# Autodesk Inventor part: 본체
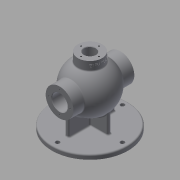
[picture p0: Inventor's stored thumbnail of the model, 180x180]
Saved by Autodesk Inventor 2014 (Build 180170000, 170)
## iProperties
Created: 2020-08
Part Number: 본체
Material: Generic
Document SubType Name: Modeling
Designer: kh
Density: 1 g/cm^3
Appearance: Default
Mass: 649.145 g
Surface Area: 1342.58 cm^2
Volume: 649.145 cm^3
Author: kh
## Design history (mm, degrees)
sketch "Sketch1"
  geometry: C1 r 85 at (0, 0); 1 further point
  constraints: 1 centre point, 1 coincident
  dimensions: "d0" = 170 diameter of C1
extrude "Extrusion1" new body sketch "Sketch1" distance "d1" = 10; taper "d2" = 0 deg
sketch "Sketch2"
  geometry: L1 (-55.535, 85)-(55.001, 85); L2 (-68, 102.5)-(-52, 102.5); L3 (-52, 102.5)-(-52, 103.5); L4 (-52, 103.5)-(-50.25, 103.5); L5 (-50.25, 103.5)-(-50.25, 102.5); L6 (-50.25, 102.5)-(-39.278, 102.5); L7 (68, 102.5)-(39.278, 102.5); L8 (-68, 102.5)-(-68, 116); L9 (-68, 116)-(-42.988, 116); L10 (68, 102.5)-(68, 116); L11 (68, 116)-(42.988, 116); A1 r 43 centre (0, 85) between (39.278, 102.5) and (-39.278, 102.5); A2 r 53 centre (0, 85) between (42.988, 116) and (-42.988, 116); 1 further point
  constraints: 22 end point, 5 perpendicular, 4 point on circle, 3 collinear, 3 parallel, 2 centre point, 2 point on line, 1 concentric, 1 horizontal, 1 vertical alignment
  dimensions: "d3" = 43 radius of A1; "d4" = 53 radius of A2; "d5" = 85 vertical distance of L1.end point (0, 0); "d6" = 35 diameter of L2 L1; "d7" = 37 diameter of L4 L1; "d8" = 35 diameter of L6 L1; "d9" = 35 diameter of L7 L1; "d10" = 62 diameter of L9 L1; "d11" = 62 diameter of L11 L1; "d12" = 16 distance of L2.start L2.end; "d13" = 1.75 distance of L3.end L4.end; "d14" = 136 distance between parallel lines of L10 L8
revolve "Revolution1" sketch "Sketch2" stored, may be unused: angle "d15" = 90 deg
workplane "Work Plane1"
sketch "Sketch3"
  geometry: C1 r 27 at (0, 0); 1 further point
  constraints: 1 centre point, 1 coincident
  dimensions: "d17" = 54 diameter of C1
extrude "Extrusion2" join sketch "Sketch3" stored distance "d18" = 10; taper "d19" = 0 deg
hole "Hole1" diameter "d22" = 26; stored, may be unused: countersink angle "d26" = 90 deg, drill point angle "d28" = 118 deg; dims "d20" = 10, "d21" = 10, "d23" = 6, "d24" = 4, "d25" = 2, "d27" = 8
sketch "Sketch4"
  geometry: L1 (85, 10)-(-85, 10) reference; L2 (-52, 10)-(-52, 35.444); L3 (52, 10)-(52, 35.444); 1 further point
  constraints: 4 end point, 2 point on line, 1 parallel, 1 perpendicular
  dimensions: "d29" = 104 distance between parallel lines of L3 L2; "d30" = 52 horizontal distance of L2.start point (0, 0)
feature "Rib1" dims "d31" = 1, "d32" = 8, "d33" = 0, "d34" = 0, "d35" = 1, "d36" = 1
feature "Rib2" dims "d37" = 1, "d38" = 8, "d39" = 0, "d40" = 0, "d41" = 1, "d42" = 1
sketch "Sketch5"
  geometry: L1 (85, 10)-(-85, 10) reference; L2 (-43, 10)-(-43, 28.251); L3 (43, 10)-(43, 30.744); 1 further point
  constraints: 4 end point, 2 point on line, 1 parallel, 1 perpendicular
  dimensions: "d43" = 86 distance between parallel lines of L3 L2; "d44" = 43 distance from line of point (0, 0) L2
feature "Rib3" dims "d45" = 1, "d46" = 8, "d47" = 0, "d48" = 0, "d49" = 1, "d50" = 1
feature "Rib4" dims "d51" = 1, "d52" = 8, "d53" = 0, "d54" = 0, "d55" = 1, "d56" = 1
workplane "Work Plane3"
sketch "Sketch7"
  geometry: L1 (-20.739, -5.998)-(20.739, -5.998); L2 (20.739, -5.998)-(20.739, -12.002); L3 (20.739, -12.002)-(-20.739, -12.002); L4 (-20.739, -12.002)-(-20.739, -5.998); L5 (-20.739, -5.998)-(20.739, -12.002); L6 (-27, 0)-(27, 0) reference; L7 (-27, 0)-(-27, -19.393) reference; 2 further points
  constraints: 2 end point, 1 midpoint, 2 other
  dimensions: "d57" = 9 distance from line of point (0, -9) L6; "d58" = 27 distance from line of point (0, -9) L7
emboss "Emboss1" sketch "Sketch7" dims "d59" = 0.5, "d60" = 0
sketch "Sketch8" dims "d61" = 48
  geometry: L1 (0, 0)-(0, 24); C1 r 31 at (0, 0) reference; 2 further points
  constraints: 2 coincident, 2 end point, 1 vertical, 1 vertical alignment, 2 other
hole "Hole2" sketch "Sketch8" at (0, 24) diameter "d62" = 3.242; stored, may be unused: countersink angle "d66" = 90 deg, drill point angle "d68" = 118 deg; dims "d63" = 12, "d64" = 4, "d65" = 2, "d67" = 15
pattern_circular "Circular Pattern1" dims angle "d70" = 360 deg
sketch "Sketch9" dims "d72" = 48
  geometry: L1 (0, 0)-(0, 24); C1 r 31 at (0, 0) reference; 2 further points
  constraints: 2 coincident, 2 end point, 1 vertical, 1 vertical alignment, 2 other
hole "Hole3" sketch "Sketch9" at (0, 24) diameter "d73" = 3.242; stored, may be unused: countersink angle "d77" = 90 deg, drill point angle "d79" = 118 deg; dims "d74" = 12, "d75" = 4, "d76" = 2, "d78" = 15
pattern_circular "Circular Pattern2" dims angle "d81" = 360 deg
sketch "Sketch10" dims "d83" = 40
  geometry: L1 (0, 0)-(0, 20); C1 r 27 at (0, 0) reference; 2 further points
  constraints: 2 coincident, 2 end point, 1 vertical, 1 vertical alignment, 2 other
hole "Hole4" sketch "Sketch10" at (0, 20) diameter "d84" = 3.242; stored, may be unused: countersink angle "d88" = 90 deg, drill point angle "d90" = 118 deg; dims "d85" = 12, "d86" = 4, "d87" = 2, "d89" = 15
pattern_circular "Circular Pattern3" dims angle "d92" = 360 deg
sketch "Sketch11" dims "d94" = 145
  geometry: L1 (0, 0)-(0, 72.5); 2 further points
  constraints: 2 coincident, 2 end point, 1 vertical, 1 vertical alignment, 2 other
hole "Hole5" sketch "Sketch11" at (0, 72.5) diameter "d95" = 9; stored, may be unused: countersink angle "d99" = 90 deg, drill point angle "d101" = 118 deg; dims "d96" = 12, "d97" = 4, "d98" = 2, "d100" = 15
pattern_circular "Circular Pattern4" dims angle "d103" = 360 deg
chamfer "Chamfer1" distance "d105" = 1; stored, may be unused: second distance "d106" = 2, angle "d107" = 45 deg
fillet "Fillet1" dims "d108" = 3
fillet "Fillet2" dims "d109" = 3
body "Solid1"
